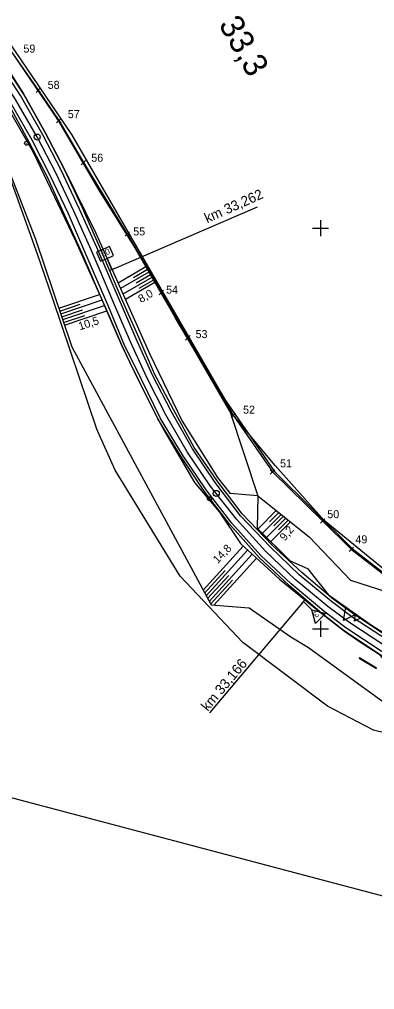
# Model space of a CAD drawing. Extents: x -805011 to -803920, y -1150790 to -1150234.
# Drawn here: x -804175.3 to -804086.5, y -1150790.1 to -1150547.8 of the extents above; entities that cross this region are included whole.
import ezdxf

# ---------------------------------------------------------------- set-up
doc = ezdxf.new("R2010")
doc.units = 0
for name, color, linetype in [('0381KM032-037P - Vrstva 1', 7, 'Continuous'), ('0381KM032-037P - Vrstva 13', 7, 'Continuous'), ('0381KM032-037P - Vrstva 17', 7, 'Continuous'), ('0381KM032-037P - Vrstva 4', 7, 'Continuous'), ('0381KM032-037P - Vrstva 48', 7, 'Continuous'), ('0381KM032-037P - Vrstva 49', 7, 'Continuous'), ('0381KM032-037P - Vrstva 5', 7, 'Continuous'), ('0381KM032-037P - Vrstva 50', 7, 'Continuous'), ('0381KM032-037P - Vrstva 7', 7, 'Continuous'), ('Default', 7, 'Continuous'), ('formát', 7, 'Continuous'), ('hran DP - hran DP', 7, 'Continuous'), ('krizky_1000 - Vrstva 1', 7, 'Continuous'), ('PSR_C2_2_Lomove_body_Vimperk - Vrstva 60', 7, 'Continuous'), ('PSR_C2_2_trasa_Vimperk - Kabelová trasa', 7, 'Continuous')]:
    doc.layers.add(name, color=color, linetype=linetype)

msp = doc.modelspace()

# ---------------------------------------------------------------- linework, layer by layer
at = {"layer": '0381KM032-037P - Vrstva 1'}
for points in [[(-804170.82, -1150577.3), (-804176.26, -1150567.85), (-804182.37, -1150558.45), (-804188.8, -1150549.63), (-804195.8, -1150541.09), (-804203.2, -1150532.98), (-804210.73, -1150525.57), (-804219.76, -1150517.68), (-804222.98, -1150515.09)], [(-804121.06, -1150672.62), (-804127.59, -1150664.31), (-804133.36, -1150655.8), (-804138.71, -1150646.59), (-804143.42, -1150637.27), (-804147.52, -1150628.35), (-804151.54, -1150619.12), (-804155.16, -1150610.64), (-804157.42, -1150605.4), (-804161.72, -1150595.74), (-804166.25, -1150586.16), (-804170.82, -1150577.3)], [(-803978.41, -1150722.71), (-803983.51, -1150723.68), (-803993.92, -1150724.91), (-804004.46, -1150725.42), (-804014.95, -1150725.21), (-804025.47, -1150724.25), (-804035.41, -1150722.67), (-804044.08, -1150720.74), (-804054.77, -1150717.61), (-804064.47, -1150714.03), (-804074.16, -1150709.61), (-804083.95, -1150704.25), (-804092.73, -1150698.52), (-804098.22, -1150694.46), (-804106.33, -1150687.73), (-804113.82, -1150680.6), (-804121.06, -1150672.62)]]:
    msp.add_lwpolyline(points, dxfattribs=at)
at = {"layer": '0381KM032-037P - Vrstva 13'}
for p, q in [((-804090.31, -1150707.26), (-804090.39, -1150707.37)), ((-804090.39, -1150707.37), (-804086.01, -1150709.92)), ((-804086.01, -1150709.9), (-804090.31, -1150707.26))]:
    msp.add_line(p, q, dxfattribs=at)
at = {"layer": '0381KM032-037P - Vrstva 17'}
for points in [[(-804099.12, -1150672.95), (-804111.38, -1150659.24), (-804122.71, -1150645.64), (-804131.91, -1150629.82), (-804136.37, -1150622.31)], [(-804059.54, -1150698.86), (-804062.04, -1150700.07), (-804077.59, -1150690.55), (-804099.12, -1150672.95)]]:
    msp.add_lwpolyline(points, dxfattribs=at)
at = {"layer": '0381KM032-037P - Vrstva 4'}
for points in [[(-804155.31, -1150604.52), (-804159.65, -1150594.76), (-804164.13, -1150585.17), (-804168.86, -1150576.08), (-804174.28, -1150566.45), (-804180.44, -1150557.11), (-804187.11, -1150547.91)], [(-804155.96, -1150604.81), (-804160.35, -1150595.07), (-804164.87, -1150585.5), (-804169.43, -1150576.62), (-804175.01, -1150566.82), (-804181.12, -1150557.55), (-804187.68, -1150548.56)], [(-804159.67, -1150606.25), (-804163.99, -1150596.78), (-804168.29, -1150587.2), (-804172.88, -1150578.5), (-804178.08, -1150568.91), (-804181.43, -1150563.5), (-804184.18, -1150559.55), (-804190.46, -1150550.87)], [(-804158.94, -1150605.89), (-804163.07, -1150596.41), (-804167.66, -1150586.77), (-804172.11, -1150577.99), (-804177.55, -1150568.56), (-804183.56, -1150559.32), (-804190.06, -1150550.44)], [(-804134.56, -1150656.61), (-804140.15, -1150647.32), (-804144.81, -1150637.78), (-804149.09, -1150628.99), (-804152.99, -1150619.67), (-804158.94, -1150605.89)], [(-804132.06, -1150655.06), (-804137.36, -1150645.71), (-804142.06, -1150636.68), (-804146.12, -1150627.62), (-804150.08, -1150618.55), (-804155.96, -1150604.81)], [(-804131.6, -1150654.76), (-804136.67, -1150645.43), (-804141.53, -1150636.36), (-804145.41, -1150627.43), (-804149.44, -1150618.25), (-804155.31, -1150604.52)], [(-804135, -1150656.89), (-804140.73, -1150647.62), (-804145.48, -1150638.07), (-804149.71, -1150629.27), (-804153.71, -1150619.99), (-804159.67, -1150606.25)], [(-804075.18, -1150711.95), (-804085.34, -1150706.36), (-804094.07, -1150700.58), (-804099.68, -1150696.17), (-804107.82, -1150689.29), (-804115.4, -1150682.25), (-804122.72, -1150674.01), (-804129.15, -1150665.64), (-804135, -1150656.89)], [(-804074.79, -1150711.15), (-804084.84, -1150705.62), (-804093.69, -1150699.81), (-804099.23, -1150695.65), (-804107.33, -1150688.8), (-804114.94, -1150681.73), (-804122.23, -1150673.64), (-804128.61, -1150665.3), (-804134.56, -1150656.61)], [(-804073.38, -1150708.29), (-804083.27, -1150702.88), (-804091.89, -1150697.28), (-804097.27, -1150693.2), (-804105.34, -1150686.53), (-804112.64, -1150679.57), (-804120.03, -1150671.79), (-804126.35, -1150663.48), (-804132.06, -1150655.06)], [(-804073.1, -1150707.59), (-804077.68, -1150705.14), (-804082.78, -1150702.25), (-804091.44, -1150696.56), (-804096.83, -1150692.65), (-804104.73, -1150685.98), (-804112.1, -1150679.17), (-804119.6, -1150671.34), (-804125.86, -1150663.1), (-804131.6, -1150654.76)]]:
    msp.add_lwpolyline(points, dxfattribs=at)
at = {"layer": '0381KM032-037P - Vrstva 48'}
for p, q in [((-804143.67, -1150609.66), (-804150.65, -1150613.69)), ((-804142.92, -1150610.96), (-804150.03, -1150615.07)), ((-804143.3, -1150610.31), (-804146.82, -1150612.35)), ((-804142.17, -1150612.26), (-804149.42, -1150616.44)), ((-804142.55, -1150611.61), (-804146.14, -1150613.68)), ((-804141.8, -1150612.91), (-804145.46, -1150615.02)), ((-804141.42, -1150613.56), (-804148.81, -1150617.82)), ((-804165.46, -1150619.97), (-804155.27, -1150616.52)), ((-804164.98, -1150621.39), (-804154.65, -1150617.89)), ((-804165.22, -1150620.68), (-804160.09, -1150618.94)), ((-804164.74, -1150622.1), (-804159.54, -1150620.34)), ((-804164.5, -1150622.81), (-804154.04, -1150619.27)), ((-804164.02, -1150624.23), (-804153.43, -1150620.64)), ((-804164.26, -1150623.52), (-804158.99, -1150621.74)), ((-804111.08, -1150670.5), (-804115.64, -1150675.08)), ((-804109.9, -1150671.45), (-804114.57, -1150676.14)), ((-804110.49, -1150670.98), (-804112.8, -1150673.29)), ((-804108.72, -1150672.39), (-804113.51, -1150677.2)), ((-804107.54, -1150673.33), (-804112.45, -1150678.26)), ((-804109.31, -1150671.92), (-804111.68, -1150674.29)), ((-804108.13, -1150672.86), (-804110.56, -1150675.3)), ((-804129.38, -1150690.39), (-804119.38, -1150679.38)), ((-804128.63, -1150691.79), (-804118.27, -1150680.39)), ((-804127.87, -1150693.19), (-804117.16, -1150681.39)), ((-804126.68, -1150694.11), (-804116.05, -1150682.4)), ((-804129.01, -1150691.09), (-804123.91, -1150685.49)), ((-804128.25, -1150692.49), (-804122.98, -1150686.69)), ((-804127.5, -1150693.89), (-804122.05, -1150687.9))]:
    msp.add_line(p, q, dxfattribs=at)
at = {"layer": '0381KM032-037P - Vrstva 49'}
for q in [(-804122.66, -1150666.25), (-804115.86, -1150674.86)]:
    msp.add_line((-804115.71, -1150666.79), q, dxfattribs=at)
for points in [[(-804216.26, -1150515.03), (-804196.49, -1150533.54), (-804188.66, -1150542.31), (-804183.72, -1150548.22), (-804177, -1150556.4), (-804165.66, -1150573.06), (-804155.49, -1150590.5), (-804146.45, -1150604.86), (-804136.37, -1150622.31), (-804131.91, -1150629.82), (-804122.71, -1150645.64), (-804115.71, -1150666.79), (-804102.89, -1150677.06), (-804092.51, -1150687.92), (-804076.71, -1150692.97), (-804062.72, -1150701.97), (-804052.08, -1150706.52)], [(-804190.46, -1150550.87), (-804184.18, -1150559.55), (-804171.89, -1150581.01)], [(-804191.88, -1150555.68), (-804187.09, -1150562.15), (-804183.47, -1150572.06), (-804177.47, -1150586.83), (-804171.32, -1150602.68), (-804162.19, -1150629.63), (-804127.41, -1150694.05), (-804117.85, -1150694.76), (-804107.49, -1150702.04), (-804103.03, -1150704.73), (-804070.42, -1150728.33), (-804053.81, -1150732.63), (-804001.62, -1150732.39)], [(-804177.46, -1150561.39), (-804174.28, -1150566.45), (-804168.86, -1150576.08), (-804164.13, -1150585.17), (-804156.2, -1150601.21), (-804142.82, -1150631.28), (-804134.64, -1150648.13), (-804125.75, -1150662.22), (-804122.66, -1150666.25)], [(-804171.89, -1150581.01), (-804161.29, -1150603.14), (-804153.71, -1150619.99), (-804149.71, -1150629.27), (-804147.81, -1150633.31), (-804145.48, -1150638.07), (-804140.73, -1150647.62), (-804139.02, -1150650.67), (-804131.55, -1150663.46), (-804125.32, -1150670.91), (-804120.07, -1150678.75), (-804110.3, -1150687.62), (-804101.36, -1150694.88), (-804099.68, -1150696.17), (-804094.07, -1150700.58), (-804090.5, -1150703.01), (-804085.34, -1150706.36), (-804081.43, -1150711.18)], [(-804115.86, -1150674.86), (-804107.6, -1150683.08), (-804103.3, -1150684.96), (-804098.16, -1150691.46), (-804087.29, -1150699.16)], [(-804087.29, -1150699.16), (-804077.68, -1150705.14), (-804077.53, -1150704.87), (-804070.24, -1150708.52), (-804052.03, -1150715.99)]]:
    msp.add_lwpolyline(points, dxfattribs=at)
at = {"layer": '0381KM032-037P - Vrstva 5'}
for p, q in [((-804152.17, -1150610.26), (-804115.82, -1150594.67)), ((-804152.87, -1150610.57), (-804151.5, -1150609.96)), ((-804104.29, -1150693.19), (-804127.82, -1150721.03)), ((-804103.76, -1150692.66), (-804104.82, -1150693.72))]:
    msp.add_line(p, q, dxfattribs=at)
for points in [[(-804152.18, -1150610.26), (-804153.41, -1150607.52), (-804151.81, -1150606.81), (-804152.83, -1150604.53), (-804156.03, -1150605.96), (-804155.01, -1150608.24), (-804153.41, -1150607.52)], [(-804104.29, -1150693.19), (-804102.17, -1150695.31), (-804098.81, -1150696.19), (-804101.28, -1150698.67), (-804102.17, -1150695.31)]]:
    msp.add_lwpolyline(points, dxfattribs=at)
at = {"layer": '0381KM032-037P - Vrstva 50'}
msp.add_lwpolyline([(-804090.07, -1150697.33), (-804091.56, -1150698.09), (-804091.28, -1150696.44), (-804094.26, -1150697.96), (-804093.69, -1150694.66)], dxfattribs=at)
at = {"layer": '0381KM032-037P - Vrstva 7'}
for p, q in [((-804173.51, -1150578.79), (-804173.56, -1150578.7)), ((-804127.76, -1150667.59), (-804127.82, -1150667.51))]:
    msp.add_line(p, q, dxfattribs=at)
for centre, radius in [((-804170.87, -1150577.21), 0.75), ((-804173.53, -1150578.75), 0.5), ((-804126.09, -1150666.21), 0.75), ((-804127.79, -1150667.55), 0.5)]:
    msp.add_circle(centre, radius, dxfattribs=at)
at = {"layer": 'formát'}
msp.add_line((-803996.25, -1150790.14), (-804199.27, -1150736.42), dxfattribs=at)
at = {"layer": 'hran DP - hran DP'}
for p, q in [((-804178.11, -1150553.27), (-804167.37, -1150569.11)), ((-804167.37, -1150569.11), (-804162.29, -1150576.56)), ((-804170.78, -1150606.46), (-804182.55, -1150573.8)), ((-804162.29, -1150576.56), (-804123.96, -1150642.72)), ((-804166.92, -1150617.84), (-804170.78, -1150606.46)), ((-804155.97, -1150650.2), (-804166.92, -1150617.84)), ((-804123.96, -1150642.72), (-804111.51, -1150660.72)), ((-804155.38, -1150651.53), (-804155.97, -1150650.2)), ((-804151.42, -1150660.42), (-804155.38, -1150651.53)), ((-804135.09, -1150686.84), (-804151.42, -1150660.42)), ((-804111.51, -1150660.72), (-804092.1, -1150680)), ((-804092.1, -1150680), (-804079.43, -1150689.81)), ((-804119.46, -1150703.45), (-804135.09, -1150686.84)), ((-804098.25, -1150719.35), (-804119.46, -1150703.45)), ((-804086.77, -1150725.31), (-804098.25, -1150719.35)), ((-804048.58, -1150734.81), (-804086.77, -1150725.31))]:
    msp.add_line(p, q, dxfattribs=at)
at = {"layer": 'krizky_1000 - Vrstva 1'}
for points in [[(-804100, -1150598), (-804100, -1150602)], [(-804102, -1150600), (-804098, -1150600)], [(-804100, -1150698), (-804100, -1150702)], [(-804102, -1150700), (-804098, -1150700)]]:
    msp.add_lwpolyline(points, dxfattribs=at)
at = {"layer": 'PSR_C2_2_Lomove_body_Vimperk - Vrstva 60'}
for p, q in [((-804171.15, -1150566.05), (-804170.05, -1150564.95)), ((-804170.05, -1150566.05), (-804171.15, -1150564.95)), ((-804166.01, -1150573.65), (-804164.91, -1150572.55)), ((-804164.91, -1150573.65), (-804166.01, -1150572.55)), ((-804159.87, -1150584.15), (-804158.77, -1150583.05)), ((-804158.77, -1150584.15), (-804159.87, -1150583.05)), ((-804148.89, -1150602), (-804147.79, -1150600.9)), ((-804147.79, -1150602), (-804148.89, -1150600.9)), ((-804140.37, -1150616.58), (-804139.27, -1150615.48)), ((-804139.27, -1150616.58), (-804140.37, -1150615.48)), ((-804133.76, -1150627.91), (-804132.66, -1150626.81)), ((-804132.66, -1150627.91), (-804133.76, -1150626.81)), ((-804122.4, -1150647.23), (-804121.3, -1150646.13)), ((-804121.3, -1150647.23), (-804122.4, -1150646.13)), ((-804112.58, -1150661.4), (-804111.48, -1150660.3)), ((-804111.48, -1150661.4), (-804112.58, -1150660.3)), ((-804100.06, -1150673.63), (-804098.96, -1150672.53)), ((-804098.96, -1150673.63), (-804100.06, -1150672.53)), ((-804092.85, -1150680.76), (-804091.75, -1150679.66)), ((-804091.75, -1150680.76), (-804092.85, -1150679.66))]:
    msp.add_line(p, q, dxfattribs=at)
at = {"layer": 'PSR_C2_2_trasa_Vimperk - Kabelová trasa'}
for points in [[(-804211.94, -1150528.21), (-804207.53, -1150523.61), (-804196.77, -1150533.52), (-804182.83, -1150549.06), (-804177, -1150556.4), (-804170.6, -1150565.5), (-804165.46, -1150573.1), (-804159.32, -1150583.6), (-804148.34, -1150601.45), (-804139.82, -1150616.03), (-804133.21, -1150627.36), (-804121.85, -1150646.68), (-804112.03, -1150660.85), (-804099.51, -1150673.08)], [(-804099.51, -1150673.08), (-804092.3, -1150680.21), (-804076.61, -1150692.29), (-804065.52, -1150700.21), (-804042.05, -1150710.07), (-804029.14, -1150713.3), (-804011.66, -1150716.99), (-803998.6, -1150718.16), (-803977.42, -1150718.41), (-803977.26, -1150718.37)]]:
    msp.add_lwpolyline(points, dxfattribs=at)

# ---------------------------------------------------------------- texts
at = {"layer": '0381KM032-037P - Vrstva 48'}
for s, rotation, p in [('8,0', 29.9889, (-804144.91, -1150618.69)), ('10,5', 18.3536, (-804160.19, -1150625.49)), ('9,2', 51.2857, (-804108.89, -1150678.22)), ('14,8', 45.8956, (-804125.73, -1150683.84))]:
    msp.add_text(s, height=2, rotation=rotation, dxfattribs=at).set_placement(p)
at = {"layer": '0381KM032-037P - Vrstva 5'}
for s, height, rotation, p in [('km 33,262', 2.5, 24.1108, (-804128.38, -1150598.75)), ('50', 1.5, 24.1108, (-804154.55, -1150607.21)), ('3', 1.5, 225.0712, (-804101.33, -1150695.53)), ('km 33,166', 2.5, 50.0712, (-804128.22, -1150720.78))]:
    msp.add_text(s, height=height, rotation=rotation, dxfattribs=at).set_placement(p)
at = {"layer": '0381KM032-037P - Vrstva 7'}
msp.add_text('33,3', height=6, rotation=299.9223, dxfattribs=at).set_placement((-804125.64, -1150549.08))
at = {"layer": 'Default'}
for s, p in [('59', (-804174.32, -1150556.11)), ('58', (-804168.25, -1150565.17)), ('57', (-804163.22, -1150572.49)), ('56', (-804157.35, -1150583.37)), ('55', (-804146.86, -1150601.78)), ('54', (-804138.64, -1150616.33)), ('53', (-804131.28, -1150627.42)), ('52', (-804119.4, -1150646.29)), ('51', (-804110.15, -1150659.7)), ('50', (-804098.34, -1150672.4)), ('49', (-804091.3, -1150678.68))]:
    msp.add_text(s, height=2, dxfattribs=at).set_placement(p)

doc.saveas('drawing.dxf')
